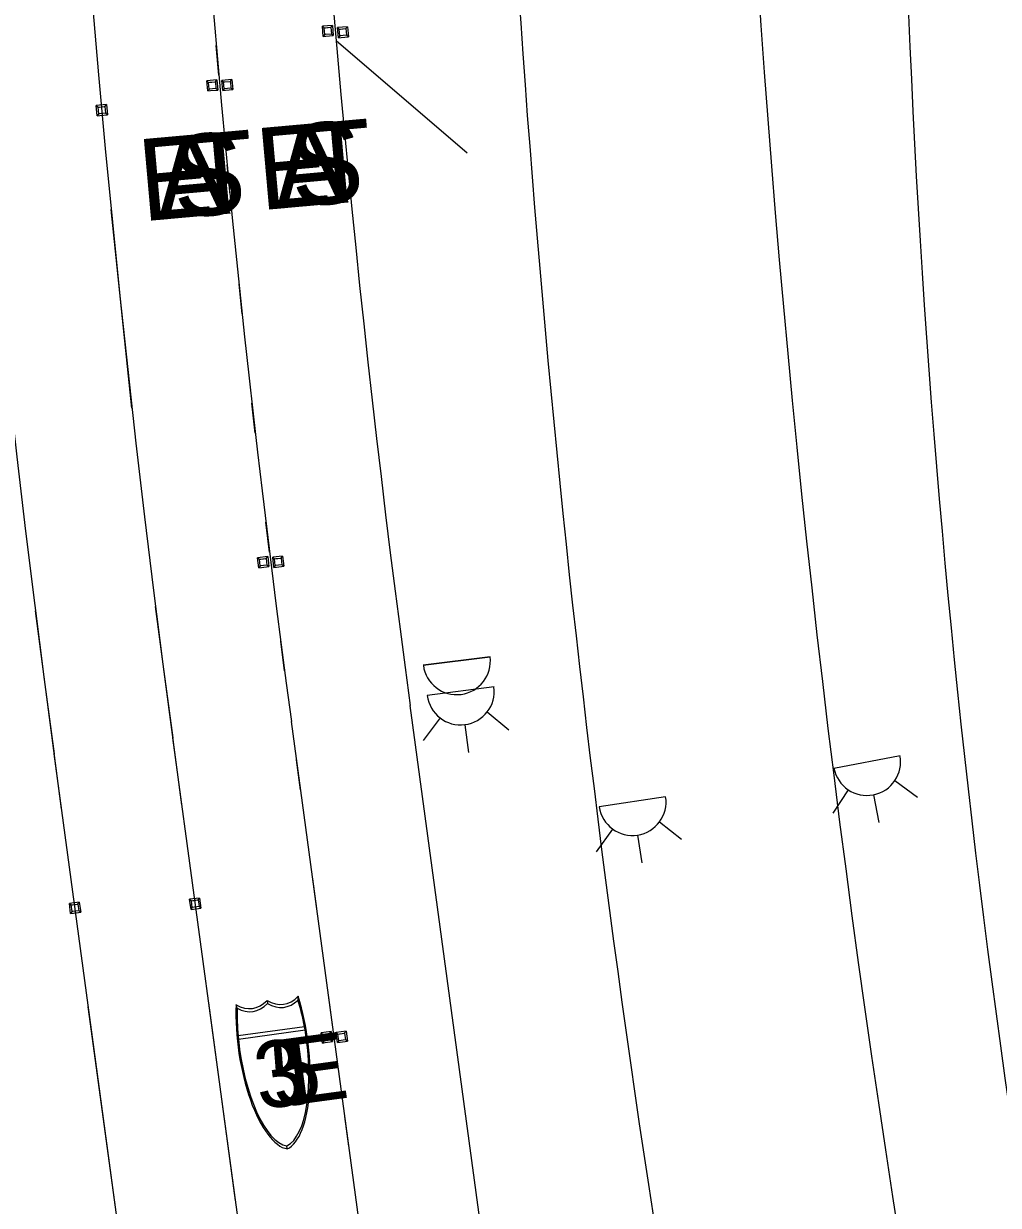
# Model space of a CAD drawing. Extents: x 2471014 to 2497726, y 6959577 to 6980268.
# Drawn here: x 2488446.4 to 2488544.1, y 6963296.9 to 6963415.2 of the extents above; entities that cross this region are included whole.
import ezdxf

# ---------------------------------------------------------------- set-up
doc = ezdxf.new("R2010")
doc.units = 0
for name, color, linetype in [('13', 7, 'Continuous'), ('18', 7, 'Continuous'), ('23', 7, 'Continuous'), ('59', 7, 'Continuous'), ('C-COMM-IDEN', 7, 'Continuous'), ('G-GRID-MAJR', 7, 'Continuous'), ('Level 30', 7, 'Continuous'), ('Level 40', 7, 'Continuous'), ('p_structure fence', 7, 'Continuous'), ('PMK_Del_D-SY_SZ_TYC_CTB', 7, 'Continuous'), ('PMK_Pav_Mark_Multi_Shield', 7, 'Continuous'), ('RDWY_PAVE_XSTREET_FOC', 7, 'Continuous'), ('V7_25', 7, 'Continuous')]:
    doc.layers.add(name, color=color, linetype=linetype)

msp = doc.modelspace()

# ---------------------------------------------------------------- linework, layer by layer
at = {"layer": '13'}
for centre, radius, start, end in [((2489874.44, 6963535.43), 1450, 149.83805, 187.72757), ((2489609.21, 6963459.85), 1075, 166.29175, 188.37964), ((2489916.91, 6963512.7), 1424, 183.42984, 191.359)]:
    msp.add_arc(centre, radius, start, end, dxfattribs=at)
at = {"layer": '18'}
msp.add_line((2488529.9, 6963017.3), (2488485.17, 6963346.91), dxfattribs=at)
for centre, radius, start, end in [((2489916.91, 6963512.7), 1400, 142.23979, 191.359), ((2489874.44, 6963535.43), 1402, 167.63271, 187.72757)]:
    msp.add_arc(centre, radius, start, end, dxfattribs=at)
at = {"layer": '23'}
for p, q in [((2488477.38, 6963414.99), (2488476.38, 6963414.91)), ((2488476.46, 6963413.9), (2488476.38, 6963414.91)), ((2488476.38, 6963414.91), (2488476.55, 6963414.75)), ((2488476.55, 6963414.75), (2488476.69, 6963414.76)), ((2488476.69, 6963414.76), (2488477.22, 6963414.81)), ((2488477.22, 6963414.81), (2488477.38, 6963414.99)), ((2488477.38, 6963414.99), (2488477.47, 6963413.98)), ((2488478.9, 6963414.87), (2488477.89, 6963414.78)), ((2488477.98, 6963413.77), (2488477.89, 6963414.78)), ((2488477.89, 6963414.78), (2488478.06, 6963414.63)), ((2488478.06, 6963414.63), (2488478.21, 6963414.64)), ((2488478.21, 6963414.64), (2488478.74, 6963414.69)), ((2488478.74, 6963414.69), (2488478.9, 6963414.87)), ((2488478.9, 6963414.87), (2488478.99, 6963413.86)), ((2488476.61, 6963414.08), (2488476.46, 6963413.9)), ((2488476.46, 6963413.9), (2488476.73, 6963413.92)), ((2488477.28, 6963414.14), (2488476.61, 6963414.08)), ((2488476.73, 6963413.92), (2488477.47, 6963413.98)), ((2488477.47, 6963413.98), (2488477.28, 6963414.14)), ((2488478.12, 6963413.95), (2488477.98, 6963413.77)), ((2488477.98, 6963413.77), (2488478.25, 6963413.8)), ((2488478.8, 6963414.01), (2488478.12, 6963413.95)), ((2488478.25, 6963413.8), (2488478.99, 6963413.86)), ((2488478.99, 6963413.86), (2488478.8, 6963414.01)), ((2488465.82, 6963409.54), (2488464.81, 6963409.45)), ((2488464.9, 6963408.44), (2488464.81, 6963409.45)), ((2488464.81, 6963409.45), (2488464.98, 6963409.3)), ((2488465.04, 6963408.62), (2488464.9, 6963408.44)), ((2488464.9, 6963408.44), (2488465.17, 6963408.47)), ((2488464.98, 6963409.3), (2488465.12, 6963409.31)), ((2488465.72, 6963408.68), (2488465.04, 6963408.62)), ((2488465.12, 6963409.31), (2488465.66, 6963409.36)), ((2488465.17, 6963408.47), (2488465.91, 6963408.53)), ((2488465.66, 6963409.36), (2488465.82, 6963409.54)), ((2488465.91, 6963408.53), (2488465.72, 6963408.68)), ((2488465.82, 6963409.54), (2488465.91, 6963408.53)), ((2488467.32, 6963409.58), (2488466.31, 6963409.49)), ((2488466.4, 6963408.48), (2488466.31, 6963409.49)), ((2488466.31, 6963409.49), (2488466.48, 6963409.34)), ((2488466.54, 6963408.66), (2488466.4, 6963408.48)), ((2488466.4, 6963408.48), (2488466.67, 6963408.51)), ((2488466.48, 6963409.34), (2488466.62, 6963409.35)), ((2488467.22, 6963408.72), (2488466.54, 6963408.66)), ((2488466.62, 6963409.35), (2488467.16, 6963409.4)), ((2488466.67, 6963408.51), (2488467.41, 6963408.57)), ((2488467.16, 6963409.4), (2488467.32, 6963409.58)), ((2488467.41, 6963408.57), (2488467.22, 6963408.72)), ((2488467.32, 6963409.58), (2488467.41, 6963408.57)), ((2488454.74, 6963407.07), (2488453.73, 6963406.98)), ((2488453.83, 6963405.96), (2488453.73, 6963406.98)), ((2488453.73, 6963406.98), (2488453.91, 6963406.82)), ((2488453.97, 6963406.15), (2488453.83, 6963405.96)), ((2488453.91, 6963406.82), (2488454.05, 6963406.83)), ((2488454.64, 6963406.21), (2488453.97, 6963406.15)), ((2488454.05, 6963406.83), (2488454.58, 6963406.88)), ((2488454.09, 6963405.99), (2488454.84, 6963406.06)), ((2488454.58, 6963406.88), (2488454.74, 6963407.07)), ((2488454.84, 6963406.06), (2488454.64, 6963406.21)), ((2488454.74, 6963407.07), (2488454.84, 6963406.06)), ((2488453.83, 6963405.96), (2488454.09, 6963405.99)), ((2488470.9, 6963361.83), (2488469.89, 6963361.71)), ((2488470.02, 6963360.7), (2488469.89, 6963361.71)), ((2488469.89, 6963361.71), (2488470.07, 6963361.56)), ((2488470.07, 6963361.56), (2488470.21, 6963361.58)), ((2488470.21, 6963361.58), (2488470.74, 6963361.64)), ((2488470.74, 6963361.64), (2488470.9, 6963361.83)), ((2488470.9, 6963361.83), (2488471.02, 6963360.83)), ((2488472.4, 6963361.87), (2488471.4, 6963361.75)), ((2488471.52, 6963360.74), (2488471.4, 6963361.75)), ((2488471.4, 6963361.75), (2488471.58, 6963361.6)), ((2488471.58, 6963361.6), (2488471.72, 6963361.62)), ((2488471.72, 6963361.62), (2488472.25, 6963361.68)), ((2488472.25, 6963361.68), (2488472.4, 6963361.87)), ((2488472.4, 6963361.87), (2488472.53, 6963360.87)), ((2488470.15, 6963360.89), (2488470.02, 6963360.7)), ((2488470.02, 6963360.7), (2488470.28, 6963360.73)), ((2488470.83, 6963360.97), (2488470.15, 6963360.89)), ((2488470.28, 6963360.73), (2488471.02, 6963360.83)), ((2488471.02, 6963360.83), (2488470.83, 6963360.97)), ((2488471.66, 6963360.93), (2488471.52, 6963360.74)), ((2488471.52, 6963360.74), (2488471.79, 6963360.77)), ((2488472.33, 6963361.01), (2488471.66, 6963360.93)), ((2488471.79, 6963360.77), (2488472.53, 6963360.87)), ((2488472.53, 6963360.87), (2488472.33, 6963361.01)), ((2488452.03, 6963327.23), (2488451.03, 6963327.1)), ((2488451.16, 6963326.09), (2488451.03, 6963327.1)), ((2488451.03, 6963327.1), (2488451.21, 6963326.95)), ((2488451.21, 6963326.95), (2488451.35, 6963326.97)), ((2488451.35, 6963326.97), (2488451.88, 6963327.04)), ((2488451.88, 6963327.04), (2488452.03, 6963327.23)), ((2488452.03, 6963327.23), (2488452.17, 6963326.23)), ((2488464.08, 6963327.64), (2488463.08, 6963327.51)), ((2488463.22, 6963326.5), (2488463.08, 6963327.51)), ((2488463.08, 6963327.51), (2488463.26, 6963327.36)), ((2488463.26, 6963327.36), (2488463.4, 6963327.38)), ((2488464.02, 6963326.78), (2488463.35, 6963326.69)), ((2488463.4, 6963327.38), (2488463.93, 6963327.45)), ((2488463.93, 6963327.45), (2488464.08, 6963327.64)), ((2488464.22, 6963326.64), (2488464.02, 6963326.78)), ((2488464.08, 6963327.64), (2488464.22, 6963326.64)), ((2488451.3, 6963326.28), (2488451.16, 6963326.09)), ((2488451.16, 6963326.09), (2488451.43, 6963326.13)), ((2488451.97, 6963326.37), (2488451.3, 6963326.28)), ((2488451.43, 6963326.13), (2488452.17, 6963326.23)), ((2488452.17, 6963326.23), (2488451.97, 6963326.37)), ((2488463.35, 6963326.69), (2488463.22, 6963326.5)), ((2488463.22, 6963326.5), (2488463.48, 6963326.54)), ((2488463.48, 6963326.54), (2488464.22, 6963326.64)), ((2488477.25, 6963314.26), (2488476.25, 6963314.13)), ((2488476.39, 6963313.12), (2488476.25, 6963314.13)), ((2488476.25, 6963314.13), (2488476.43, 6963313.98)), ((2488476.43, 6963313.98), (2488476.57, 6963314)), ((2488476.57, 6963314), (2488477.1, 6963314.07)), ((2488477.1, 6963314.07), (2488477.25, 6963314.26)), ((2488477.25, 6963314.26), (2488477.39, 6963313.26)), ((2488478.76, 6963314.3), (2488477.76, 6963314.17)), ((2488477.89, 6963313.16), (2488477.76, 6963314.17)), ((2488477.76, 6963314.17), (2488477.94, 6963314.02)), ((2488477.94, 6963314.02), (2488478.08, 6963314.04)), ((2488478.08, 6963314.04), (2488478.61, 6963314.11)), ((2488478.61, 6963314.11), (2488478.76, 6963314.3)), ((2488478.76, 6963314.3), (2488478.9, 6963313.3)), ((2488476.52, 6963313.31), (2488476.39, 6963313.12)), ((2488476.39, 6963313.12), (2488476.65, 6963313.16)), ((2488477.19, 6963313.4), (2488476.52, 6963313.31)), ((2488476.65, 6963313.16), (2488477.39, 6963313.26)), ((2488477.39, 6963313.26), (2488477.19, 6963313.4)), ((2488478.03, 6963313.35), (2488477.89, 6963313.16)), ((2488477.89, 6963313.16), (2488478.16, 6963313.2)), ((2488478.7, 6963313.44), (2488478.03, 6963313.35)), ((2488478.16, 6963313.2), (2488478.9, 6963313.3)), ((2488478.9, 6963313.3), (2488478.7, 6963313.44))]:
    msp.add_line(p, q, dxfattribs=at)
for points in [[(2488476.61, 6963414.08), (2488476.55, 6963414.75), (2488477.22, 6963414.81), (2488477.28, 6963414.14)], [(2488478.12, 6963413.95), (2488478.06, 6963414.63), (2488478.74, 6963414.69), (2488478.8, 6963414.01)], [(2488465.04, 6963408.62), (2488464.98, 6963409.3), (2488465.66, 6963409.36), (2488465.72, 6963408.68)], [(2488466.54, 6963408.66), (2488466.48, 6963409.34), (2488467.16, 6963409.4), (2488467.22, 6963408.72)], [(2488453.97, 6963406.15), (2488453.91, 6963406.82), (2488454.58, 6963406.88), (2488454.64, 6963406.21)], [(2488470.15, 6963360.89), (2488470.07, 6963361.56), (2488470.74, 6963361.64), (2488470.83, 6963360.97)], [(2488471.66, 6963360.93), (2488471.58, 6963361.6), (2488472.25, 6963361.68), (2488472.33, 6963361.01)], [(2488451.3, 6963326.28), (2488451.21, 6963326.95), (2488451.88, 6963327.04), (2488451.97, 6963326.37)], [(2488463.35, 6963326.69), (2488463.26, 6963327.36), (2488463.93, 6963327.45), (2488464.02, 6963326.78)], [(2488476.52, 6963313.31), (2488476.43, 6963313.98), (2488477.1, 6963314.07), (2488477.19, 6963313.4)], [(2488478.03, 6963313.35), (2488477.94, 6963314.02), (2488478.61, 6963314.11), (2488478.7, 6963313.44)]]:
    msp.add_lwpolyline(points, close=True, dxfattribs=at)
at = {"layer": '59'}
msp.add_line((2488518, 6963015.69), (2488473.28, 6963345.3), dxfattribs=at)
msp.add_arc((2489874.44, 6963535.43), 1414, 167.6301, 187.72757, dxfattribs=at)
at = {"layer": 'C-COMM-IDEN'}
for p, q in [((2488486.49, 6963350.94), (2488493.19, 6963351.8)), ((2488493.19, 6963351.8), (2488486.49, 6963350.94)), ((2488493.58, 6963348.77), (2488486.88, 6963347.91)), ((2488492.9, 6963346.28), (2488495.06, 6963344.48)), ((2488488.17, 6963345.67), (2488486.48, 6963343.42)), ((2488490.66, 6963344.99), (2488491.02, 6963342.2))]:
    msp.add_line(p, q, dxfattribs=at)
for centre in [(2488489.84, 6963351.37), (2488490.23, 6963348.34)]:
    msp.add_arc(centre, 3.37, 187.3291, 7.3291, dxfattribs=at)
at = {"layer": 'G-GRID-MAJR'}
msp.add_line((2488477.75, 6963413.49), (2488490.89, 6963402.26), dxfattribs=at)
at = {"layer": 'Level 30'}
for p, q in [((2488527.63, 6963340.64), (2488534.25, 6963341.92)), ((2488533.74, 6963339.39), (2488536.01, 6963337.73)), ((2488529.05, 6963338.48), (2488527.51, 6963336.13)), ((2488531.58, 6963337.97), (2488532.12, 6963335.2))]:
    msp.add_line(p, q, dxfattribs=at)
msp.add_arc((2488530.94, 6963341.28), 3.37, 190.9767, 10.9767, dxfattribs=at)
at = {"layer": 'Level 40'}
for p, q in [((2488466.01, 6963410.01), (2488465.75, 6963413)), ((2488467.13, 6963398.06), (2488466.84, 6963401.05)), ((2488468.34, 6963386.12), (2488468.03, 6963389.1)), ((2488469.66, 6963374.19), (2488469.32, 6963377.17)), ((2488471.08, 6963362.28), (2488470.71, 6963365.26)), ((2488472.6, 6963350.37), (2488472.21, 6963353.35)), ((2488474.2, 6963338.48), (2488473.8, 6963341.46)), ((2488475.82, 6963326.59), (2488475.41, 6963329.56)), ((2488477.43, 6963314.7), (2488477.03, 6963317.67)), ((2488479.04, 6963302.81), (2488478.64, 6963305.78))]:
    msp.add_line(p, q, dxfattribs=at)
at = {"layer": 'PMK_Del_D-SY_SZ_TYC_CTB'}
for p, q in [((2488510.77, 6963337.78), (2488504.1, 6963336.76)), ((2488510.16, 6963335.28), (2488512.36, 6963333.53)), ((2488505.44, 6963334.55), (2488503.8, 6963332.26)), ((2488507.95, 6963333.94), (2488508.37, 6963331.16))]:
    msp.add_line(p, q, dxfattribs=at)
msp.add_arc((2488507.44, 6963337.27), 3.37, 188.7063, 8.7063, dxfattribs=at)
at = {"layer": 'PMK_Pav_Mark_Multi_Shield'}
for p, q in [((2488470.84, 6963317.38), (2488470.89, 6963317.07)), ((2488473.94, 6963317.42), (2488473.95, 6963317.8)), ((2488473.95, 6963317.8), (2488473.94, 6963317.42)), ((2488467.85, 6963316.6), (2488467.74, 6963316.96)), ((2488467.85, 6963316.6), (2488467.74, 6963316.96)), ((2488474.59, 6963314.73), (2488467.94, 6963313.83)), ((2488467.94, 6963313.83), (2488467.97, 6963313.52)), ((2488467.97, 6963313.52), (2488474.64, 6963314.43)), ((2488474.59, 6963314.73), (2488474.64, 6963314.43)), ((2488474.64, 6963314.43), (2488474.59, 6963314.73)), ((2488472.86, 6963302.52), (2488472.82, 6963302.83))]:
    msp.add_line(p, q, dxfattribs=at)
for centre, major_axis, start_param, end_param in [((2488467.35, 6963331.44), (-2.02, 14.86), 2.857844, 3.425344), ((2488470.46, 6963331.86), (-2.02, 14.86), 2.857844, 3.425344), ((2488470.47, 6963331.87), (-2.06, 15.17), 2.862234, 3.405964), ((2488470.98, 6963312.91), (-1.43, 10.53), 3.259514, 5.144414), ((2488470.98, 6963312.91), (-1.39, 10.22), 4.841111, 5.118585), ((2488471.9, 6963313.04), (-1.43, 10.53), 1.138774, 3.023674), ((2488471.9, 6963313.04), (-1.39, 10.22), 1.164604, 1.442074), ((2488467.34, 6963331.44), (-2.06, 15.17), 2.877224, 3.420954), ((2488470.98, 6963312.91), (-1.39, 10.22), 3.263084, 4.810824), ((2488471.9, 6963313.03), (-1.39, 10.22), 1.472354, 3.020104)]:
    msp.add_ellipse(centre, major_axis=major_axis, ratio=0.373432, start_param=start_param, end_param=end_param, dxfattribs=at)
at = {"layer": 'RDWY_PAVE_XSTREET_FOC'}
for p, q in [((2488457.3, 6963376.67), (2488455.21, 6963396.56)), ((2488450.24, 6963336.57), (2488447.63, 6963356.4)), ((2488462.3, 6963336.98), (2488459.67, 6963356.81)), ((2488455.62, 6963296.93), (2488452.93, 6963316.75)), ((2488467.67, 6963297.35), (2488464.99, 6963317.16))]:
    msp.add_line(p, q, dxfattribs=at)
at = {"layer": 'V7_25'}
for p, q in [((2488506.11, 6963014.07), (2488461.39, 6963343.69)), ((2488494.22, 6963012.46), (2488449.5, 6963342.07))]:
    msp.add_line(p, q, dxfattribs=at)
for radius in [1438, 1426]:
    msp.add_arc((2489874.44, 6963535.43), radius, 149.83805, 187.72757, dxfattribs=at)

# ---------------------------------------------------------------- texts
at = {"layer": 'p_structure fence'}
for s, p in [('E', (2488470.15, 6963396.49)), ('A', (2488471.77, 6963396.63)), ('S', (2488473.47, 6963396.79)), ('T', (2488475.07, 6963396.93)), ('E', (2488458.33, 6963395.38)), ('A', (2488459.94, 6963395.52)), ('S', (2488461.65, 6963395.67)), ('T', (2488463.24, 6963395.82))]:
    msp.add_text(s, height=8.2, rotation=5.1125, dxfattribs=at).set_placement(p)
at = {"layer": 'PMK_Pav_Mark_Multi_Shield'}
for s, p in [('5', (2488471.63, 6963306.66)), ('E', (2488473.32, 6963306.89)), ('3', (2488470.02, 6963306.44))]:
    msp.add_text(s, height=6.67, rotation=7.7274, dxfattribs=at).set_placement(p)

doc.saveas('drawing.dxf')
